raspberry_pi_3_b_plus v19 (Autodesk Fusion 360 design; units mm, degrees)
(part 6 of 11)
sketch "Sketch4" plane through (0, 0, 15.35) normal (0, 0, 1) x axis (-1, 0, 0)
  line L1 (8.5, -21.1878) -> (0.78, -21.1878)
  line L2 (8.5, -6.6286) -> (8.5, -15.9536)
  line L3 (-7.9, -6.6286) -> (8.5, -6.6286)
  line L4 (-7.9, -7.1286) -> (-7.9, -6.6286)
  line L5 (-7.9, -19.2786) -> (-7.9, -7.1286)
  line L6 (-7.9, -19.7786) -> (-7.9, -19.2786)
  line L7 (0.28, -19.7786) -> (-7.9, -19.7786)
  line L8 (0.78, -21.1878) -> (0.78, -19.7786)
  line L9 (7.9563, -25.2118) -> (8.5, -20.7835)
  line L10 (6.5097, -21.514) -> (6.9637, -25.2118)
  line L11 (2.9803, -21.014) -> (6.2597, -21.014)
  line L12 (2.7303, -21.514) -> (2.7303, -21.264)
  line L13 (2.2763, -25.2118) -> (2.7303, -21.514)
  line L14 (0.78, -21.414) -> (0.78, -23.8331)
  line L15 (0.78, -21.1092) -> (1.2837, -25.2118)
  line L16 (7.46, -21.7371) -> (7.46, -25.1508)
  line L17 (8.5, -25.6508) -> (0.78, -25.6508)
  line L18 (6.5097, -21.514) -> (6.5097, -21.264)
  line L19 (1.78, -21.9964) -> (1.78, -25.1508)
  line L20 (0.78, -21.414) -> (8.5, -21.414)
  line L21 (19.0131, 0) -> (0, 0)
  line L22 (7.9563, 25.2118) -> (8.5, 20.7835)
  line L23 (6.5097, 21.514) -> (6.9637, 25.2118)
  line L24 (6.5097, 21.514) -> (6.5097, 21.264)
  line L25 (2.9803, 21.014) -> (6.2597, 21.014)
  line L26 (2.7303, 21.514) -> (2.7303, 21.264)
  line L27 (2.2763, 25.2118) -> (2.7303, 21.514)
  line L28 (0.78, 21.1092) -> (1.2837, 25.2118)
  line L29 (0.78, 21.414) -> (0.78, 23.8331)
  line L30 (0.78, 23.8331) -> (0.78, 24.3609)
  line L31 (0.78, 24.3609) -> (0.78, 25.6508)
  line L32 (0.78, 25.6508) -> (8.5, 25.6508)
  line L33 (8.5, 25.6508) -> (8.5, 24.3609)
  line L34 (8.5, 24.3609) -> (8.5, 23.8331)
  line L35 (8.5, 21.414) -> (8.5, 23.8331)
  line L36 (8.5, 21.1878) -> (8.5, 21.414)
  line L37 (8.5, -24.3609) -> (8.5, -25.6508)
  line L38 (8.5, -23.8331) -> (8.5, -24.3609)
  line L39 (8.5, -21.414) -> (8.5, -23.8331)
  line L40 (0.78, -25.6508) -> (0.78, -24.3609)
  line L41 (0.78, -24.3609) -> (0.78, -23.8331)
  line L42 (8.5, -21.1878) -> (8.5, -21.414)
  line L43 (-7.9, 26.3572) -> (0.28, 26.3572)
  line L44 (0.28, 26.3572) -> (-7.9, 26.3572)
  line L45 (-4.9, 27.3428) -> (-4.9, 26.3572)
  line L46 (-5.5626, 27.3572) -> (-4.2374, 27.3572)
  line L47 (-4.2929, 26.6611) -> (-4.0642, 27.0572)
  line L48 (-5.5071, 26.6611) -> (-5.7358, 27.0572)
  line L49 (-7.9, 20.9572) -> (-7.9, 26.3572)
  line L50 (-4.15, 26.3572) -> (-4.1962, 26.3763)
  line L51 (-5.65, 26.3572) -> (-5.6038, 26.3763)
  line L52 (-5.7256, -26.3572) -> (-5.7015, -26.3472)
  line L53 (-5.629, -26.1336) -> (-5.8665, -25.7222)
  line L54 (-5.65, -25.3472) -> (-4.15, -25.3472)
  line L55 (-4.171, -26.1336) -> (-3.9335, -25.7222)
  line L56 (-4.0744, -26.3572) -> (-4.0985, -26.3472)
  line L57 (0.28, -26.3572) -> (-7.9, -26.3572)
  line L58 (-4.9, -26.3572) -> (-4.9, -25.3472)
  line L59 (-7.9, -26.3572) -> (-7.9, -20.9572)
  line L60 (-8.5786, 5.45) -> (-9.2286, 5.45)
  line L61 (-9.2286, -5.45) -> (-9.2286, 5.45)
  line L62 (-8.5786, 7.1286) -> (-9.2286, 7.1286)
  line L63 (-9.2286, 7.1286) -> (-9.2286, 19.2786)
  line L64 (-8.5786, 19.2786) -> (-9.2286, 19.2786)
  line L65 (-8.5786, -5.45) -> (-9.2286, -5.45)
  line L66 (-8.5786, -7.1286) -> (-9.2286, -7.1286)
  line L67 (-8.5786, 26.3572) -> (-9.2286, 26.3572)
  line L68 (-9.2286, 26.3572) -> (-9.2286, 20.9572)
  line L69 (-9.2286, 20.9572) -> (-9.2286, 26.3572)
  line L70 (-9.2286, 20.9572) -> (-8.5786, 20.9572)
  line L71 (-8.5786, 20.9572) -> (-9.2286, 20.9572)
  line L72 (-9.2286, -7.1286) -> (-9.2286, -19.2786)
  line L73 (-9.2286, -19.2786) -> (-8.5786, -19.2786)
  line L74 (-9.2286, -19.2786) -> (-9.2286, -7.1286)
  line L75 (-8.5786, -20.9572) -> (-9.2286, -20.9572)
  line L76 (-9.2286, -20.9572) -> (-9.2286, -26.3572)
  line L77 (-9.2286, -26.3572) -> (-8.5786, -26.3572)
  line L78 (-9.2286, -26.3572) -> (-9.2286, -20.9572)
  line L79 (-6.9525, -16.1966) -> (-6.9525, -18.2105)
  line L80 (-1.8477, -16.2319) -> (-6.8739, -15.7036)
  line L81 (-1.4, -17.6781) -> (-1.4, -16.7291)
  line L82 (-6.8739, -18.7036) -> (-1.8477, -18.1753)
  line L83 (-1.8477, -8.2319) -> (-6.8739, -7.7036)
  line L84 (-1.4, -9.6781) -> (-1.4, -8.7291)
  line L85 (-6.8739, -10.7036) -> (-1.8477, -10.1753)
  line L86 (-6.9525, -8.1966) -> (-6.9525, -10.2105)
  line L87 (2.5, -16.3786) -> (2.5, -18.0786)
  line L88 (4.2, -16.3786) -> (2.5, -16.3786)
  line L89 (4.2, -18.0786) -> (4.2, -16.3786)
  line L90 (2.5, -18.0786) -> (4.2, -18.0786)
  line L91 (-3.125, -12.5786) -> (-3.125, -13.8286)
  line L92 (4.225, -12.5786) -> (-3.125, -12.5786)
  line L93 (4.225, -13.8286) -> (4.225, -12.5786)
  line L94 (-3.125, -13.8286) -> (4.225, -13.8286)
  line L95 (6.5, -10.8536) -> (6.5, -13.5536)
  line L96 (7.35, -10.7036) -> (6.65, -10.7036)
  line L97 (7.5, -13.5536) -> (7.5, -10.8536)
  line L98 (6.65, -13.7036) -> (7.35, -13.7036)
  line L99 (2.5, -8.3286) -> (2.5, -10.0286)
  line L100 (4.2, -8.3286) -> (2.5, -8.3286)
  line L101 (4.2, -10.0286) -> (4.2, -8.3286)
  line L102 (2.5, -10.0286) -> (4.2, -10.0286)
  line L103 (8.5, -18.4536) -> (8.5, -21.1878)
  line L104 (8, -16.4536) -> (8, -17.9536)
  line L105 (8.5, 21.1878) -> (8.5, 18.4536)
  line L106 (8.5, -6.6286) -> (8.5, -15.9536)
  line L107 (8.5, 15.9536) -> (8.5, 6.6286)
  line L108 (8.5, -18.4536) -> (8.5, -21.1878)
  line L109 (-7.9, -20.9572) -> (-8.5786, -20.9572)
  line L110 (-7.9, -20.4572) -> (-7.9, -20.9572)
  line L111 (-7.9, -20.9572) -> (-7.9, -20.4572)
  line L112 (-7.9, -19.2786) -> (-8.5786, -19.2786)
  line L113 (-7.9, -7.1286) -> (-8.5786, -7.1286)
  line L114 (-7.9, -5.45) -> (-8.5786, -5.45)
  line L115 (-7.9, -5.45) -> (-7.9, -5.95)
  line L116 (-7.9, 5.45) -> (-8.5786, 5.45)
  line L117 (-7.9, 5.95) -> (-7.9, 5.45)
  line L118 (-7.9, 7.1286) -> (-8.5786, 7.1286)
  line L119 (-7.9, 7.1286) -> (-7.9, 6.6286)
  line L120 (-7.9, 19.2786) -> (-8.5786, 19.2786)
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  point P12 (8.5, -20.7835)
  point P28 (0.78, -21.1092)
  point P15 (7.46, -25.1508)
  point P30 (7.46, -25.1508)
  point P25 (1.78, -25.1508)
  point P34 (1.78, -25.1508)
  point P16 (6.5097, -21.514)
  point P22 (2.7303, -21.514)
  point P1 (0, 0)
  point P37 (0, 0)
  point P39 (8.5, 20.7835)
  point P13 (7.9563, -25.2118)
  point P40 (7.9563, 25.2118)
  point P14 (6.9637, -25.2118)
  point P42 (6.9637, 25.2118)
  point P43 (6.5097, 21.514)
  point P17 (6.2597, -21.014)
  point P46 (6.2597, 21.014)
  point P19 (2.9803, -21.014)
  point P47 (2.9803, 21.014)
  point P20 (2.7303, -21.264)
  point P49 (2.7303, 21.264)
  point P50 (2.7303, 21.514)
  point P23 (2.2763, -25.2118)
  point P51 (2.2763, 25.2118)
  point P24 (1.2837, -25.2118)
  point P53 (1.2837, 25.2118)
  point P54 (0.78, 21.1092)
  point P29 (6.5097, -21.264)
  point P44 (6.5097, 21.264)
  point P71 (-4.9, 26.3572)
  point P73 (-4.1962, 26.3763)
  point P82 (-5.6038, 26.3763)
  point P74 (-4.2929, 26.6611)
  point P81 (-5.5071, 26.6611)
  point P76 (-4.2374, 27.3572)
  point P85 (-5.5626, 27.3572)
  point P79 (-4.0642, 27.0572)
  point P83 (-5.7358, 27.0572)
  point P78 (-5.5626, 27.3572)
  point P87 (-4.15, 26.3572)
  point P88 (-5.65, 26.3572)
  point P105 (-4.9, -25.3472)
  point P106 (-4.9, -26.3572)
  point P90 (-5.7015, -26.3472)
  point P101 (-4.0985, -26.3472)
  point P92 (-5.629, -26.1336)
  point P99 (-4.171, -26.1336)
  point P93 (-5.8665, -25.7222)
  point P98 (-3.9335, -25.7222)
  point P89 (-5.7256, -26.3572)
  point P102 (-4.0744, -26.3572)
  point P119 (-9.2286, 25.8572)
  point P118 (-8.7286, 26.3572)
  point P127 (-9.2286, 21.4572)
  point P126 (-8.7286, 20.9572)
  point P132 (-9.2286, 18.7786)
  point P131 (-8.7286, 19.2786)
  point P135 (-9.2286, 7.6286)
  point P134 (-8.7286, 7.1286)
  point P138 (-9.2286, 4.95)
  point P137 (-8.7286, 5.45)
  point P141 (-9.2286, -4.95)
  point P140 (-8.7286, -5.45)
  point P144 (-9.2286, -7.6286)
  point P143 (-8.7286, -7.1286)
  point P149 (-9.2286, -18.7786)
  point P148 (-8.7286, -19.2786)
  point P153 (-8.7286, -20.9572)
  point P160 (-9.2286, -25.8572)
  point P159 (-8.7286, -26.3572)
  point P154 (-9.2286, -21.4572)
  point P240 (-7.9, -19.4286)
  point P239 (-8.05, -19.2786)
  point P245 (-7.9, -6.9786)
  point P244 (-8.05, -7.1286)
  point P248 (-8.05, -5.45)
  point P255 (-7.9, 5.6)
  point P254 (-8.05, 5.45)
  point P261 (-7.9, 6.9786)
  point P260 (-8.05, 7.1286)
  point P266 (-8.05, 19.2786)
  point P232 (-8.05, -20.9572)
  point P233 (-7.9, -20.8072)
  point P249 (-7.9, -5.6)
  point P94 (-5.65, -25.5972)
  point P97 (-4.15, -25.5972)
  coincident L2 P12
  coincident L14 P28
  horizontal L11
  vertical L12
  coincident P15 P30
  vertical L16
  vertical L18
  coincident P25 P34
  vertical L19
  horizontal P16 P22
  coincident P1 P37
  horizontal L21
  symmetric P12 L21 P39
  symmetric P13 L21 P40
  symmetric P14 L21 P42
  symmetric P16 L21 P43
  symmetric P17 L21 P46
  symmetric P19 L21 P47
  symmetric P20 L21 P49
  symmetric P22 L21 P50
  symmetric P23 L21 P51
  symmetric P24 L21 P53
  symmetric P28 L21 P54
  symmetric P29 L21 P44
  coincident L43 P71
  vertical L45
  horizontal L46
  symmetric L45 P73 P82
  symmetric L45 P74 P81
  symmetric L45 P76 P85
  symmetric L45 P79 P83
  coincident P78 P85
  coincident L43 P87
  coincident L43 P88
  midpoint L54 P105
  coincident L57 P106
  vertical L58
  horizontal L54
  symmetric P90 P101 L58
  symmetric P92 P99 L58
  symmetric P93 P98 L58
  coincident P89 L57
  coincident P102 L57
  coincident P119 L68
  coincident P118 L67
  coincident L68 P127
  coincident P126 L70
  coincident L63 P132
  coincident L64 P131
  coincident L63 P135
  coincident L62 P134
  coincident L61 P138
  coincident L60 P137
  coincident L61 P141
  coincident L65 P140
  coincident P144 L72
  coincident L66 P143
  coincident L72 P149
  coincident P148 L73
  coincident P153 L75
  coincident L76 P160
  coincident P159 L77
  coincident P154 L76
  coincident L6 P240
  coincident P239 L112
  coincident L4 P245
  coincident P244 L113
  coincident P248 L114
  coincident P255 L117
  coincident P254 L116
  coincident P261 L119
  coincident P260 L118
  coincident P266 L120
  coincident P232 L109
  coincident P233 L111
  coincident P249 L115
  dimension "d73_4" angle L9 L16 = 7
  dimension "d74_4" angle L10 L16 = 7 (= "d73_4")
  dimension "d75_3" radius = 0.5
  dimension "d77_2" angle L13 L19 = 7 (= "d73_4")
  dimension "d78_2" angle L15 L19 = 7 (= "d73_4")
  dimension "d79_3" distance L11 L20 = 0.4
  dimension "d80_3" radius = 0.25
  dimension "d81_3" distance P16 L11 = 0.5
  dimension "d82_4" distance L16 L19 = 5.68
  dimension "d86_3" distance L44 L46 = 1
  dimension "d87_3" radius = 0.2
  dimension "d89_4" angle L45 L47 = 30
  dimension "d91_4" distance L45 L49 = 3
  dimension "d92_4" distance P82 P88 = 0.05
  dimension "d93_3" distance P87 P88 = 1.5
  dimension "d94_3" angle L43 L51 = 22.5
  dimension "d98_3" angle L53 L58 = 30
  dimension "d99_3" angle L55 L58 = 30
  dimension "d102_3" radius = 0.25
  dimension "d103_3" radius = 0.25
  dimension "d104_3" radius = 0.15
  dimension "d105_2" radius = 0.15
  dimension "d107_3" distance P90 L54 = 1
  dimension "d108_3" distance P94 P97 = 1.5
  dimension "d111_3" distance P90 L57 = 0.01
  dimension "d112_3" angle L52 L57 = 22.5
  dimension "d113_3" distance L58 L59 = 3
  dimension "d115_2" radius = 0.5
  dimension "d224_2" radius = 0.15 (= "d1_4 / 2")
  dimension "d287_2" distance L2 L19 = 6.72 (= "d3_3 - 10.28 mm")
extrude "Extrude4" cut sketch "Sketch4" no distance stored
extrude "Extrude5" add sketch "Sketch4" to an object
extrude "Extrude6" cut sketch "Sketch4" no distance stored
step "Refold1"
face "EdgeFlange9" FlangeHeight 0.85 (= "1 mm - d1_4 / 2") named "d63_4" FlangeAngle 30 named "d64_4"
face "EdgeFlange10" FlangeHeight 1.75 named "d65_4" FlangeAngle 75 named "d66_3"
face "EdgeFlange18" FlangeHeight 1.5 named "d225_3" FlangeAngle 45 named "d226_2"
face "EdgeFlange15" FlangeHeight 1.5 named "d191_2" FlangeAngle 20 named "d192_3" BendWidth 0.1 named "d282_4" BendDepth 0.15 named "d283_4" BendRemnant 0.6 named "d284_1"
face "EdgeFlange16" FlangeHeight 0.601 (= "2 * d1_4 + 0.001 mm") named "d193_3" FlangeAngle 45 named "d194_2" BendWidth 0.05 named "d195_3" BendDepth 0 named "d196_2" BendRemnant 0 named "d197_2"
face "EdgeFlange17" FlangeHeight 3.0015 named "d200_2" FlangeAngle 45 named "d201_2"
step "Unfold2"
extrude "Extrude3" cut sketch "Sketch3" no distance stored
step "Refold2"
sketch "Sketch1" plane through (-8.5, 0, 0) normal (-1, 0, 0) x axis (0, -1, 0)
  line L1 (-6.25, 14.75) -> (-6.25, 5.425)
  line L2 (-6.55, 14.75) -> (-6.25, 14.75)
  line L3 (-6.55, 5.425) -> (-6.55, 14.75)
  line L4 (6.85, 3.3) -> (5.875, 3.3)
  line L5 (5.875, 2.6127) -> (5.875, 1.5)
  line L6 (6.85, 5.05) -> (6.85, 3.3)
  line L7 (5.875, 5.05) -> (6.85, 5.05)
  line L8 (-5.65, 13.04) -> (-5.65, 14.7)
  line L9 (5.65, 14.7) -> (5.65, 13.04)
  line L10 (-5.65, 14.7) -> (5.65, 14.7)
  line L11 (5.74, 12.95) -> (5.74, 5.6179)
  line L12 (5.875, 1.5) -> (-5.875, 1.5)
  line L13 (-5.875, 1.5) -> (-5.875, 2.6127)
  line L14 (-5.74, 5.6179) -> (-5.74, 12.95)
  line L15 (-5.875, 3.3) -> (-6.85, 3.3)
  line L16 (-6.85, 5.05) -> (-5.875, 5.05)
  line L17 (-6.85, 3.3) -> (-6.85, 5.05)
  line L18 (0, 1.5) -> (0, 14.7)
  line L19 (-3.7701, 15.05) -> (3.7701, 15.05)
  line L20 (6.55, 14.25) -> (6.55, 2.1)
  line L21 (-6.25, 5.425) -> (-6.55, 5.425)
  line L22 (-6.25, 0.5951) -> (-6.55, 0.5951)
  line L23 (-6.25, 2.925) -> (-6.25, 0.5951)
  line L24 (-6.55, 2.925) -> (-6.25, 2.925)
  line L25 (-6.55, 0.5951) -> (-6.55, 2.925)
  arc A1 centre (-5.875, 3) radius 0.3 clockwise from (-5.875, 3.3) to (-5.8, 2.7095)
  arc A2 centre (-5.775, 2.6127) radius 0.1 clockwise from (-5.875, 2.6127) to (-5.8, 2.7095)
  arc A3 centre (5.875, 3) radius 0.3 clockwise from (5.8, 2.7095) to (5.875, 3.3)
  arc A4 centre (5.775, 2.6127) radius 0.1 clockwise from (5.8, 2.7095) to (5.875, 2.6127)
  arc A5 centre (-5.875, 5.35) radius 0.3 clockwise from (-5.74, 5.6179) to (-5.875, 5.05)
  arc A6 centre (5.875, 5.35) radius 0.3 clockwise from (5.875, 5.05) to (5.74, 5.6179)
  arc A7 centre (-5.74, 13.04) radius 0.09 clockwise from (-5.65, 13.04) to (-5.74, 12.95)
  arc A8 centre (5.74, 13.04) radius 0.09 clockwise from (5.74, 12.95) to (5.65, 13.04)
  point P24 (0, 14.7)
  point P25 (0, 1.5)
  point P1 (0, 0)
  point P10 (-5.74, 12.95)
  point P14 (5.74, 12.95)
  point P19 (5.74, 5.6179)
  point P20 (-5.74, 5.6179)
  point P11 (-6.85, 5.05)
  point P23 (6.85, 5.05)
  point P15 (-6.85, 3.3)
  point P18 (6.85, 3.3)
  point P28 (6.85, 4.175)
  point P31 (6.55, 8.175)
  point P8 (-5.875, 2.6127)
  point P38 (-5.875, 2.6127)
  point P37 (-5.875, 3)
  point P7 (-5.875, 3.3)
  point P42 (5.875, 3.3)
  point P36 (-5.8, 2.7095)
  point P41 (5.8, 2.7095)
  point P44 (5.875, 2.6127)
  point P17 (5.875, 2.6127)
  point P46 (-5.875, 5.35)
  point P45 (-5.74, 5.6179)
  point P47 (5.875, 5.35)
  point P48 (-5.74, 12.95)
  point P49 (-5.74, 13.04)
  point P51 (5.74, 13.04)
  point P9 (-5.875, 1.5)
  point P12 (5.875, 1.5)
  point P30 (6.55, 14.25)
  horizontal L10
  vertical L8
  vertical L14
  vertical L17
  horizontal L12
  vertical L11
  vertical L9
  vertical L13
  vertical L5
  vertical L6
  perpendicular L15 L17
  perpendicular L16 L17
  perpendicular L4 L6
  perpendicular L6 L7
  midpoint L10 P24
  midpoint L12 P25
  vertical L18
  vertical P1 P25
  symmetric P10 P14 L18
  symmetric P19 P20 L18
  symmetric P11 P23 L18
  symmetric P15 P18 L18
  midpoint L6 P28
  midpoint L20 P31
  tangent L15 A1
  tangent A1 A2
  coincident P8 P38
  coincident L13 P37
  tangent L13 A2
  symmetric P7 L18 P42
  symmetric L18 P36 P41
  symmetric L18 A1 A3
  symmetric L18 P38 P44
  symmetric L18 A2 A4
  coincident P17 P44
  tangent L16 A5
  coincident L13 P46
  equal A1 A5
  coincident P20 P45
  tangent L7 A6
  equal A1 A6
  symmetric L18 P46 P47
  tangent L8 A7
  coincident P10 P48
  tangent L9 A8
  coincident L14 P49
  coincident L11 P51
  dimension "d141_2" distance L10 L12 = 13.2
  dimension "d147_2" distance L4 L7 = 1.75
  dimension "d153_3" distance P9 P12 = 11.75
  dimension "d156_3" distance L6 L17 = 13.7 (= "13.10 mm + 2 * d1_4")
  dimension "d158_3" distance L1 L8 = 0.6 (= "2 * d1_4")
  dimension "d159_3" distance L10 L19 = 0.35 (= "d1_4 + 0.05 mm")
  dimension "d175_2" distance P28 P31 = 4
  dimension "d208_3" radius A1 = 0.3 (= "d1_4")
  dimension "d209_3" radius A2 = 0.1
  dimension "d217_2" distance P14 P30 = 0.81 (= "2.7 * d1_4")
  dimension "d218_3" distance P14 L10 = 1.75
face "Face1" sketch "Sketch1"
face "EdgeFlange3" FlangeHeight 1.5 named "d168_2" FlangeAngle 90 named "d169_2" BendRadius 0.2 named "d170_3"
face "EdgeFlange4" FlangeHeight 2.5 named "d214_3" FlangeAngle 90 named "d215_3" BendRemnant 0.6 named "d219_2" BendRadius 0.2 named "d220_2"
face "EdgeFlange5" FlangeHeight 2 named "d221_2" FlangeAngle 90 named "d222_2"
base_feature "Base Feature1"
work_plane "WorkPlane1" AlongDistance 8.05 named "d228_3"
sketch "Sketch1" plane through (8.05, 0, 0) normal (1, 0, 0) x axis (0, 1, 0)
  line L1 (-6.2, 9.975) -> (6.2, 9.975)
  line L2 (-6.2, 6.375) -> (-6.2, 9.975)
  line L3 (6.2, 6.375) -> (-6.2, 6.375)
  line L4 (6.2, 9.975) -> (6.2, 6.375)
  line L5 (-6.2, 6.375) -> (6.2, 9.975)
  line L6 (6.2, 6.375) -> (-6.2, 9.975)
  line L7 (-4.6, 7.675) -> (-1.1, 7.675)
  line L8 (-4.6, 8.675) -> (-4.6, 7.675)
  line L9 (-1.1, 8.675) -> (-4.6, 8.675)
  line L10 (-1.1, 7.675) -> (-1.1, 8.675)
  line L11 (-4.6, 8.675) -> (-1.1, 7.675)
  line L12 (-1.1, 8.675) -> (-4.6, 7.675)
  line L13 (0, 9.4362) -> (0, 8.175)
  line L14 (1.1, 8.675) -> (4.6, 8.675)
  line L15 (1.1, 7.675) -> (1.1, 8.675)
  line L16 (4.6, 7.675) -> (1.1, 7.675)
  line L17 (4.6, 8.675) -> (4.6, 7.675)
  point P6 (0, 8.175)
  point P1 (0, 0)
  point P7 (-6.55, 8.175)
  point P12 (-2.85, 8.175)
  point P13 (0, 8.175)
  point P8 (-1.1, 7.675)
  point P17 (1.1, 7.675)
  point P9 (-4.6, 7.675)
  point P18 (4.6, 7.675)
  point P10 (-4.6, 8.675)
  point P15 (4.6, 8.675)
  point P11 (-1.1, 8.675)
  point P16 (1.1, 8.675)
  point P4 (-6.2, 6.375)
  point P5 (6.2, 6.375)
  point P3 (-6.2, 9.975)
  perpendicular L1 L2
  parallel L1 L3
  parallel L2 L4
  horizontal L1
  coincident L5 P6
  coincident L6 P6
  vertical P1 P6
  horizontal P6 P7
  perpendicular L7 L8
  parallel L7 L9
  parallel L8 L10
  horizontal L7
  coincident L11 P12
  coincident L12 P12
  coincident P6 P13
  vertical L13
  symmetric P8 L13 P17
  symmetric P9 L13 P18
  symmetric P10 L13 P15
  symmetric P11 L13 P16
  horizontal P6 P12
  dimension "d229_3" distance P4 P5 = 12.4
  dimension "d230_2" distance P3 P4 = 3.6 (= "3 mm + d1_4 * 2")
  dimension "d231_2" distance P10 P11 = 3.5
  dimension "d232_3" distance P9 P10 = 1
  dimension "d233_3" distance L10 L13 = 1.1
face "Face1" sketch "Sketch1"
face "EdgeFlange2" FlangeHeight 8.5 named "d234_3" FlangeAngle 90 named "d235_3"
extrude "Extrude6" cut sketch "Sketch1" profile of L7 L8 L9 L10 L14 L15 L16 L17 no distance stored
face "EdgeFlange3" FlangeHeight 2.5 named "d236_3" FlangeAngle 20 named "d237_3" BendRemnant 0 named "d240_3" BendWidth 0.01 named "d243_3" BendDepth 0 named "d244_3"
face "EdgeFlange4" FlangeHeight 1 named "d241_3" FlangeAngle 20 (= "d237_3") named "d242_3"
sketch "Sketch3" plane through (0, 0, 9.975) normal (0, 0, 1) x axis (-1, 0, 0)
  line L1 (-7.75, -6.2) -> (-7.75, 6.2)
  line L2 (0.15, -6.2) -> (-7.75, -6.2)
  line L3 (0.15, 6.2) -> (0.15, -6.2)
  line L4 (-7.75, 6.2) -> (0.15, 6.2)
  line L5 (-7.35, -2.132) -> (-7.35, -3.868)
  line L6 (-7.0487, -4.2146) -> (-2.35, -4.875)
  line L7 (-2.35, -3) -> (-7.35, -3)
  line L8 (-2.35, -1.125) -> (-2.35, -4.875)
  line L9 (-7.0487, -1.7854) -> (-2.35, -1.125)
  line L10 (-8.35, 6.2) -> (-8.35, -6.2)
  line L11 (-13, 0) -> (0, 0)
  line L12 (-7.0487, 1.7854) -> (-2.35, 1.125)
  line L13 (-7.35, 2.132) -> (-7.35, 3.868)
  line L14 (-7.0487, 4.2146) -> (-2.35, 4.875)
  line L15 (-2.35, 1.125) -> (-2.35, 4.875)
  arc A1 centre (-7, -3.868) radius 0.35 clockwise from (-7.0487, -4.2146) to (-7.35, -3.868)
  arc A2 centre (-7, -2.132) radius 0.35 clockwise from (-7.35, -2.132) to (-7.0487, -1.7854)
  arc A3 centre (-7, 2.132) radius 0.35 clockwise from (-7.0487, 1.7854) to (-7.35, 2.132)
  arc A4 centre (-7, 3.868) radius 0.35 clockwise from (-7.35, 3.868) to (-7.0487, 4.2146)
  point P14 (-2.35, -1.125)
  point P15 (-2.35, -4.875)
  point P16 (-2.35, -1.125)
  point P7 (-7.35, -3)
  point P6 (-7.0487, -1.7854)
  point P12 (-7.0487, -4.2146)
  point P17 (-2.35, -3)
  point P1 (0, 0)
  point P21 (0, 0)
  point P24 (-7.0487, 1.7854)
  point P10 (-7.35, -3.868)
  point P27 (-7.35, 3.868)
  point P29 (-7.0487, 4.2146)
  point P13 (-7.35, -2.132)
  point P26 (-7.35, 2.132)
  point P23 (-2.35, 1.125)
  point P30 (-2.35, 4.875)
  point P31 (-2.35, 1.125)
  point P9 (-2.35, 3)
  symmetric P14 P15 L7
  coincident P14 P16
  coincident P7 L5
  tangent L6 A1
  tangent L5 A1
  tangent L5 A2
  tangent A2 L9
  equal A1 A2
  symmetric P6 P12 L7
  coincident P17 L8
  coincident P1 P21
  horizontal L11
  symmetric P6 L11 P24
  symmetric P10 L11 P27
  symmetric P12 L11 P29
  symmetric P13 L11 P26
  symmetric P14 L11 P23
  symmetric P15 L11 P30
  symmetric P16 L11 P31
  symmetric A1 L11 A4
  symmetric A2 L11 A3
  midpoint P9 L15
  dimension "d260_3" distance P9 L7 = 6
  dimension "d261_2" angle L6 L8 = 82
  dimension "d262_2" radius A1 = 0.35
  dimension "d263_2" distance L5 L8 = 5
  dimension "d264_4" distance P15 P16 = 3.75
  dimension "d265_4" distance L5 L10 = 1
extrude "Extrude2" cut sketch "Sketch3" profile of L5 L6 A1 L8 A2 L9 L12 A3 L13 A4 L14 L15 no distance stored
face "EdgeFlange6" FlangeHeight 2.5 named "d267_4" FlangeAngle 10 named "d268_4" BendWidth 0.5 named "d269_4" BendDepth 0.3 named "d270_4" BendRemnant 0.6 named "d271_4"
step "Unfold2"
sketch "Sketch4" plane through (8.35, 0, 0) normal (1, 0, 0) x axis (0, 1, 0)
  line L1 (6.2, 6.975) -> (-6.2, 6.975)
  line L2 (6.2, 9.375) -> (6.2, 6.975)
  line L3 (-6.2, 9.375) -> (6.2, 9.375)
  line L4 (-6.2, 6.975) -> (-6.2, 9.375)
  line L5 (-3.7536, 11.1257) -> (-4.3774, 15.5646)
  line L6 (-2.4445, 10.9536) -> (-3.5555, 10.9536)
  line L7 (-1.6226, 15.5646) -> (-2.2464, 11.1257)
  line L8 (-1.7854, 10.7549) -> (-1.1601, 15.2036)
  line L9 (-4.8399, 15.2036) -> (-4.2146, 10.7549)
  line L10 (-3.868, 10.4536) -> (-2.132, 10.4536)
  line L11 (-4.875, 15.4536) -> (-4.8399, 15.2036)
  line L12 (-4.875, 15.5298) -> (-4.875, 15.2036)
  line L13 (-4.875, 15.2036) -> (-4.875, 15.5298)
  line L14 (-4.875, 15.2036) -> (-4.8399, 15.2036)
  line L15 (-1.125, 15.4536) -> (-1.1601, 15.2036)
  line L16 (-1.125, 15.2036) -> (-1.125, 15.5298)
  line L17 (-1.125, 15.5298) -> (-1.125, 15.2036)
  line L18 (-1.1601, 15.2036) -> (-1.125, 15.2036)
  line L19 (0, 22.1983) -> (0, 0)
  line L20 (4.875, 15.2036) -> (4.875, 15.5298)
  line L21 (1.125, 15.5298) -> (1.125, 15.2036)
  line L22 (1.125, 15.2036) -> (1.1601, 15.2036)
  line L23 (4.8399, 15.2036) -> (4.875, 15.2036)
  line L24 (1.1601, 15.2036) -> (1.125, 15.2036)
  line L25 (1.1601, 15.2036) -> (1.7854, 10.7549)
  line L26 (2.132, 10.4536) -> (3.868, 10.4536)
  line L27 (4.2146, 10.7549) -> (4.8399, 15.2036)
  line L28 (1.125, 15.4536) -> (1.1601, 15.2036)
  line L29 (4.875, 15.4536) -> (4.8399, 15.2036)
  line L30 (3.7536, 11.1257) -> (4.3774, 15.5646)
  line L31 (2.4445, 10.9536) -> (3.5555, 10.9536)
  line L32 (1.6226, 15.5646) -> (2.2464, 11.1257)
  line L33 (6.2, 8.175) -> (-6.2, 8.175)
  line L34 (-3.7536, 5.2243) -> (-4.3774, 0.7854)
  line L35 (-2.4445, 5.3964) -> (-3.5555, 5.3964)
  line L36 (-1.6226, 0.7854) -> (-2.2464, 5.2243)
  line L37 (3.7536, 5.2243) -> (4.3774, 0.7854)
  line L38 (2.4445, 5.3964) -> (3.5555, 5.3964)
  line L39 (1.6226, 0.7854) -> (2.2464, 5.2243)
  line L40 (-4.875, 0.8964) -> (-4.8399, 1.1464)
  line L41 (-1.125, 0.8964) -> (-1.1601, 1.1464)
  line L42 (1.125, 0.8964) -> (1.1601, 1.1464)
  line L43 (4.875, 0.8964) -> (4.8399, 1.1464)
  line L44 (-4.875, 1.1464) -> (-4.875, 0.8202)
  line L45 (-4.8399, 1.1464) -> (-4.875, 1.1464)
  line L46 (-4.2146, 5.5951) -> (-4.8399, 1.1464)
  line L47 (-1.1601, 1.1464) -> (-1.7854, 5.5951)
  line L48 (-1.125, 0.8202) -> (-1.125, 1.1464)
  line L49 (-1.125, 1.1464) -> (-1.1601, 1.1464)
  line L50 (-2.132, 5.8964) -> (-3.868, 5.8964)
  line L51 (1.125, 1.1464) -> (1.125, 0.8202)
  line L52 (1.1601, 1.1464) -> (1.125, 1.1464)
  line L53 (1.7854, 5.5951) -> (1.1601, 1.1464)
  line L54 (4.875, 0.8202) -> (4.875, 1.1464)
  line L55 (4.875, 1.1464) -> (4.8399, 1.1464)
  line L56 (4.8399, 1.1464) -> (4.2146, 5.5951)
  line L57 (3.868, 5.8964) -> (2.132, 5.8964)
  arc A1 centre (-3.5555, 11.1536) radius 0.2 clockwise from (-3.5555, 10.9536) to (-3.7536, 11.1257)
  arc A2 centre (-2.4445, 11.1536) radius 0.2 clockwise from (-2.2464, 11.1257) to (-2.4445, 10.9536)
  arc A3 centre (-4.625, 15.5298) radius 0.25 clockwise from (-4.875, 15.5298) to (-4.375, 15.5298)
  arc A4 centre (-1.375, 15.5298) radius 0.25 clockwise from (-1.625, 15.5298) to (-1.125, 15.5298)
  arc A5 centre (-1.375, 15.5298) radius 0.25 clockwise from (-1.625, 15.5298) to (-1.125, 15.5298)
  arc A6 centre (-3.868, 10.8036) radius 0.35 clockwise from (-3.868, 10.4536) to (-4.2146, 10.7549)
  arc A7 centre (-2.132, 10.8036) radius 0.35 clockwise from (-1.7854, 10.7549) to (-2.132, 10.4536)
  arc A8 centre (1.375, 15.5298) radius 0.25 clockwise from (1.125, 15.5298) to (1.625, 15.5298)
  arc A9 centre (4.625, 15.5298) radius 0.25 clockwise from (4.375, 15.5298) to (4.875, 15.5298)
  arc A10 centre (2.132, 10.8036) radius 0.35 clockwise from (2.132, 10.4536) to (1.7854, 10.7549)
  arc A11 centre (3.868, 10.8036) radius 0.35 clockwise from (4.2146, 10.7549) to (3.868, 10.4536)
  arc A12 centre (3.5555, 11.1536) radius 0.2 clockwise from (3.7536, 11.1257) to (3.5555, 10.9536)
  arc A13 centre (2.4445, 11.1536) radius 0.2 clockwise from (2.4445, 10.9536) to (2.2464, 11.1257)
  arc A14 centre (-3.5555, 5.1964) radius 0.2 clockwise from (-3.7536, 5.2243) to (-3.5555, 5.3964)
  arc A15 centre (-2.4445, 5.1964) radius 0.2 clockwise from (-2.4445, 5.3964) to (-2.2464, 5.2243)
  arc A16 centre (3.5555, 5.1964) radius 0.2 clockwise from (3.5555, 5.3964) to (3.7536, 5.2243)
  arc A17 centre (2.4445, 5.1964) radius 0.2 clockwise from (2.2464, 5.2243) to (2.4445, 5.3964)
  arc A18 centre (-4.625, 0.8202) radius 0.25 clockwise from (-4.375, 0.8202) to (-4.875, 0.8202)
  arc A19 centre (-1.375, 0.8202) radius 0.25 clockwise from (-1.125, 0.8202) to (-1.625, 0.8202)
  arc A20 centre (-2.132, 5.5464) radius 0.35 clockwise from (-2.132, 5.8964) to (-1.7854, 5.5951)
  arc A21 centre (-3.868, 5.5464) radius 0.35 clockwise from (-4.2146, 5.5951) to (-3.868, 5.8964)
  arc A22 centre (1.375, 0.8202) radius 0.25 clockwise from (1.625, 0.8202) to (1.125, 0.8202)
  arc A23 centre (4.625, 0.8202) radius 0.25 clockwise from (4.875, 0.8202) to (4.375, 0.8202)
  arc A24 centre (2.132, 5.5464) radius 0.35 clockwise from (1.7854, 5.5951) to (2.132, 5.8964)
  arc A25 centre (3.868, 5.5464) radius 0.35 clockwise from (3.868, 5.8964) to (4.2146, 5.5951)
  point P17 (-4.8399, 15.2036)
  point P20 (-4.8399, 15.2036)
  point P21 (-4.875, 15.4536)
  point P6 (-4.3774, 15.5646)
  point P13 (-1.6226, 15.5646)
  point P14 (-1.1601, 15.2036)
  point P34 (-1.1601, 15.2036)
  point P35 (-1.125, 15.4536)
  point P1 (0, 0)
  point P38 (0, 0)
  point P53 (1.1601, 15.2036)
  point P60 (1.1601, 15.2036)
  point P51 (4.8399, 15.2036)
  point P62 (4.8399, 15.2036)
  point P63 (4.875, 15.4536)
  point P61 (1.125, 15.4536)
  point P64 (4.3774, 15.5646)
  point P7 (-3.7536, 11.1257)
  point P65 (3.7536, 11.1257)
  point P8 (-3.5555, 10.9536)
  point P67 (3.5555, 10.9536)
  point P10 (-2.4445, 10.9536)
  point P68 (2.4445, 10.9536)
  point P11 (-2.2464, 11.1257)
  point P70 (2.2464, 11.1257)
  point P71 (1.6226, 15.5646)
  point P72 (-6.2, 8.175)
  point P73 (6.2, 8.175)
  point P74 (-4.3774, 0.7854)
  point P75 (-3.7536, 5.2243)
  point P77 (-3.5555, 5.3964)
  point P78 (-2.4445, 5.3964)
  point P80 (-2.2464, 5.2243)
  point P81 (-1.6226, 0.7854)
  point P90 (-4.8399, 1.1464)
  point P91 (-4.875, 0.8964)
  point P92 (-1.1601, 1.1464)
  point P93 (-1.125, 0.8964)
  point P94 (1.1601, 1.1464)
  point P95 (1.125, 0.8964)
  point P96 (4.8399, 1.1464)
  point P97 (4.875, 0.8964)
  point P82 (4.3774, 0.7854)
  point P83 (3.7536, 5.2243)
  point P85 (3.5555, 5.3964)
  point P86 (2.4445, 5.3964)
  point P88 (2.2464, 5.2243)
  point P89 (1.6226, 0.7854)
  tangent L5 A1
  tangent L6 A2
  parallel L7 L8
  parallel L5 L9
  parallel L6 L10
  tangent A2 L7
  tangent A1 L6
  coincident P17 P20
  parallel L9 L11
  coincident P21 L12
  coincident P6 A3
  tangent L5 A3
  coincident P13 A4
  tangent L7 A5
  coincident P14 P34
  parallel L8 L15
  coincident P35 L16
  coincident P1 P38
  vertical L19
  equal A1 A2
  coincident P53 P60
  parallel L25 L28
  coincident P51 P62
  parallel L27 L29
  coincident L20 P63
  coincident L21 P61
  symmetric P6 L19 P64
  symmetric P7 L19 P65
  symmetric P8 L19 P67
  symmetric A1 L19 A12
  symmetric P10 L19 P68
  symmetric P11 L19 P70
  symmetric A2 L19 A13
  symmetric P13 L19 P71
  midpoint L4 P72
  midpoint L2 P73
  symmetric P6 L33 P74
  symmetric P7 L33 P75
  symmetric P8 L33 P77
  symmetric A1 L33 A14
  symmetric P10 L33 P78
  symmetric P11 L33 P80
  symmetric A2 L33 A15
  symmetric P13 L33 P81
  symmetric P20 L33 P90
  symmetric P21 L33 P91
  symmetric P34 L33 P92
  symmetric P35 L33 P93
  symmetric P60 L33 P94
  symmetric P61 L33 P95
  symmetric P62 L33 P96
  symmetric P63 L33 P97
  symmetric P64 L33 P82
  symmetric P65 L33 P83
  symmetric P67 L33 P85
  symmetric A12 L33 A16
  symmetric P68 L33 P86
  symmetric P70 L33 P88
  symmetric A13 L33 A17
  symmetric P71 L33 P89
  dimension "d272_4" distance L6 L10 = 0.5
  dimension "d273_4" radius A1 = 0.2
extrude "Extrude3" add sketch "Sketch4" profile of L11 L12 L13 L14 L15 L16 L17 L18 L20 L21 L22 L23 L24 L28 L29 L40 L41 L42 L43 L44 L45 L48 L49 L51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 against normal blind 0.3 named "d274_4"
extrude "Extrude4" cut sketch "Sketch4" profile of L5 A1 L6 A2 L7 L8 L9 L10 L11 L12 L13 A3 A4 A5 L15 L16 L17 A6 A7 A8 A9 L20 L21 L25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 no distance stored
step "Refold2"
face "EdgeFlange7" FlangeHeight 0.75 named "d277_4" FlangeAngle 30 named "d278_4"
face "EdgeFlange8" FlangeHeight 2 named "d279_4" FlangeAngle 72 named "d280_4"
step "Unfold3"
extrude "Extrude5" cut sketch "Sketch4" profile of L5 A1 L6 A2 L7 L8 L9 L10 L11 L12 L13 A3 A4 A5 L15 L16 L17 A6 A7 A8 A9 L20 L21 L25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 no distance stored
step "Refold3"
work_plane "WorkPlane1" AlongDistance -15.76 (= "-10.28 mm - 2.71 mm - 2.62 mm - 0.15 mm") named "d288_2"
sketch "Sketch1" plane through (-7.26, 0, 15.975) normal (1, 0, 0) x axis (0, 1, 0)
  line L1 (3.8, -18.2428) -> (3.5893, -18.775)
  line L2 (3.8, -2.175) -> (3.8, -13.7834)
  line L3 (3.2, -13.7834) -> (3.2, -2.175)
  line L4 (3.8, -15.1666) -> (3.8, -18.2428)
  line L5 (3.9928, -14.3132) -> (3.8, -14.475)
  line L6 (3.2, -18.2533) -> (3.2, -15.1666)
  line L7 (3.2, -2.175) -> (3.8, -2.175)
  line L8 (3.5893, -18.775) -> (3.4107, -18.775)
  line L9 (3.4107, -18.775) -> (3.2, -18.2533)
  line L10 (3.7701, -0.925) -> (-3.7701, -0.925)
  line L11 (3.5, -18.775) -> (3.5, -2.175)
  line L12 (3.2, -14.475) -> (3.8, -14.475)
  line L13 (3.9928, -14.6368) -> (3.8, -14.475)
  line L14 (3.0072, -14.3132) -> (3.2, -14.475)
  line L15 (3.0072, -14.6368) -> (3.2, -14.475)
  arc A1 centre (3.8, -14.0834) radius 0.3 clockwise from (3.8, -13.7834) to (3.9928, -14.3132)
  arc A2 centre (3.8, -14.8666) radius 0.3 clockwise from (3.9928, -14.6368) to (3.8, -15.1666)
  arc A3 centre (3.2, -14.0834) radius 0.3 clockwise from (3.0072, -14.3132) to (3.2, -13.7834)
  arc A4 centre (3.2, -14.8666) radius 0.3 clockwise from (3.2, -15.1666) to (3.0072, -14.6368)
  point P5 (3.8, -14.0834)
  point P8 (3.8, -14.475)
  point P6 (3.9928, -14.3132)
  point P9 (3.9928, -14.3132)
  point P19 (3.5, -2.175)
  point P20 (3.5, -18.775)
  point P23 (3.9928, -14.6368)
  point P25 (3.8, -14.475)
  point P26 (3.9928, -14.6368)
  point P14 (3.8, -13.7834)
  point P24 (3.8, -15.1666)
  point P13 (3.8, -15.1666)
  point P28 (3.0072, -14.3132)
  point P30 (3.2, -14.475)
  point P31 (3.0072, -14.3132)
  point P29 (3.2, -13.7834)
  point P36 (3.0072, -14.6368)
  point P35 (3.2, -15.1666)
  point P32 (3.2, -14.475)
  point P33 (3.0072, -14.6368)
  point P4 (3.2, -13.7834)
  point P12 (3.2, -15.1666)
  point P21 (3.2, -14.475)
  point P18 (0, -15.975)
  point P1 (0, 0)
  vertical L3
  vertical L2
  coincident P5 L2
  coincident P8 L2
  collinear L2 L4
  collinear L3 L6
  horizontal L8
  horizontal L7
  coincident P6 P9
  tangent A1 L5
  midpoint L7 P19
  midpoint L8 P20
  horizontal L12
  symmetric P6 L12 P23
  symmetric P8 L12 P25
  symmetric P9 L12 P26
  symmetric P14 L12 P24
  symmetric A1 L12 A2
  coincident P23 P26
  coincident P13 P24
  coincident P8 P25
  symmetric P6 L11 P28
  symmetric P8 L11 P30
  symmetric P9 L11 P31
  symmetric P14 L11 P29
  symmetric A1 L11 A3
  symmetric L11 P23 P36
  symmetric L11 P24 P35
  symmetric L11 A2 A4
  symmetric L11 P25 P32
  symmetric L11 P26 P33
  coincident P4 P29
  coincident P12 P35
  coincident P21 P30
  dimension "d289_2" distance L2 L3 = 0.6
  dimension "d293_2" distance L7 L10 = 1.25
  dimension "d295_2" distance L8 P18 = 2.8
  dimension "d298_2" angle L2 L5 = 50
  dimension "d299_2" radius A1 = 0.3
  dimension "d300_2" distance P18 L12 = 1.5
  dimension "d301_2" distance P1 L11 = 3.5 (= "( 7 / 2 ) * 1 mm")
face "Face1" sketch "Sketch1"
face "EdgeFlange2" FlangeHeight 4 named "d302_2" FlangeAngle 90 named "d303_2"
sketch "Sketch2" plane through (0, 0, 13.8) normal (0, 0, 1) x axis (-1, 0.0001, 0)
  line L1 (6.9604, -3.1991) -> (6.9605, -3.7992)
  line L2 (3.5604, -3.1996) -> (6.9604, -3.1991)
  line L3 (3.5605, -3.7996) -> (3.5604, -3.1996)
  line L4 (6.9605, -3.7992) -> (3.5605, -3.7996)
  line L5 (7.5605, -3.7991) -> (7.5604, -3.1991)
  line L6 (2.7854, -4.1587) -> (2.7354, -4.1587)
  line L7 (3.9604, -4.0649) -> (3.9604, -4.1089)
  line L8 (2.1854, -4.1587) -> (1.4604, -4.1587)
  line L9 (2.9747, -4.2241) -> (2.8668, -4.176)
  line L10 (3.8604, -4.2089) -> (3.528, -4.2089)
  line L11 (3.4515, -4.2241) -> (2.9747, -4.2241)
  line L12 (1.4604, -4.1587) -> (1.4604, -2.8394)
  line L13 (7.5604, -3.4991) -> (1.4604, -3.4991)
  line L14 (6.9605, -3.7992) -> (3.5605, -3.7996)
  line L15 (2.1854, -2.8394) -> (1.4604, -2.8394)
  line L16 (2.7854, -2.8394) -> (2.7354, -2.8394)
  line L17 (2.9747, -2.7741) -> (2.8668, -2.8221)
  line L18 (3.4515, -2.7741) -> (2.9747, -2.7741)
  line L19 (3.8604, -2.7893) -> (3.528, -2.7893)
  line L20 (3.9604, -2.9332) -> (3.9604, -2.8893)
  line L21 (1.3604, -4.1319) -> (1.0901, -3.9759)
  line L22 (1.4604, -4.1587) -> (1.4604, -4.1587)
  line L23 (0.45, -3.9491) -> (0.9901, -3.9491)
  line L24 (1.3604, -2.8662) -> (1.0901, -3.0223)
  line L25 (0.9901, -3.9491) -> (0.9901, -3.0491)
  line L26 (3.5605, -3.7996) -> (3.5604, -3.1996)
  line L27 (0.8339, -4.1587) -> (1.4604, -4.1587)
  line L28 (0.8339, -2.8339) -> (0.8339, -4.1587)
  line L29 (1.4604, -2.8394) -> (0.8339, -2.8339)
  arc A1 centre (3.528, -4.4089) radius 0.2 clockwise from (3.4515, -4.2241) to (3.528, -4.2089)
  arc A2 centre (4.2269, -3.6495) radius 0.15 clockwise from (4.2269, -3.7995) to (4.1436, -3.7743)
  arc A3 centre (4.0604, -3.8991) radius 0.15 clockwise from (3.9354, -3.982) to (4.1436, -3.7743)
  arc A4 centre (3.8104, -4.0649) radius 0.15 clockwise from (3.9354, -3.982) to (3.9604, -4.0649)
  arc A5 centre (3.8604, -4.1089) radius 0.1 clockwise from (3.9604, -4.1089) to (3.8604, -4.2089)
  arc A6 centre (2.7854, -4.3587) radius 0.2 clockwise from (2.7854, -4.1587) to (2.8668, -4.176)
  arc A7 centre (2.7354, -4.3587) radius 0.2 clockwise from (2.5979, -4.2135) to (2.7354, -4.1587)
  arc A8 centre (2.4604, -4.0683) radius 0.2 clockwise from (2.5979, -4.2135) to (2.3229, -4.2135)
  arc A9 centre (2.1854, -4.3587) radius 0.2 clockwise from (2.1854, -4.1587) to (2.3229, -4.2135)
  arc A10 centre (2.1854, -2.6394) radius 0.2 clockwise from (2.3229, -2.7847) to (2.1854, -2.8394)
  arc A11 centre (2.7354, -2.6394) radius 0.2 clockwise from (2.7354, -2.8394) to (2.5979, -2.7847)
  arc A12 centre (2.7854, -2.6394) radius 0.2 clockwise from (2.8668, -2.8221) to (2.7854, -2.8394)
  arc A13 centre (3.528, -2.5893) radius 0.2 clockwise from (3.528, -2.7893) to (3.4515, -2.7741)
  arc A14 centre (3.8604, -2.8893) radius 0.1 clockwise from (3.8604, -2.7893) to (3.9604, -2.8893)
  arc A15 centre (3.8104, -2.9332) radius 0.15 clockwise from (3.9604, -2.9332) to (3.9354, -3.0162)
  arc A16 centre (4.0604, -3.0991) radius 0.15 clockwise from (4.1436, -3.2239) to (3.9354, -3.0162)
  arc A17 centre (4.2269, -3.3487) radius 0.15 clockwise from (4.1436, -3.2239) to (4.2269, -3.1987)
  arc A18 centre (2.4604, -2.9299) radius 0.2 clockwise from (2.3229, -2.7847) to (2.5979, -2.7847)
  arc A19 centre (1.4604, -3.9587) radius 0.2 clockwise from (1.4604, -4.1587) to (1.3604, -4.1319)
  arc A20 centre (0.9901, -4.1491) radius 0.2 clockwise from (0.9901, -3.9491) to (1.0901, -3.9759)
  arc A21 centre (0.9901, -2.8491) radius 0.2 clockwise from (1.0901, -3.0223) to (0.9901, -3.0491)
  arc A22 centre (1.4604, -3.0394) radius 0.2 clockwise from (1.3604, -2.8662) to (1.4604, -2.8394)
  point P32 (2.7604, -4.1587)
  point P35 (1.4604, -3.4991)
  point P33 (2.3229, -4.2135)
  point P37 (2.3229, -4.2135)
  point P36 (7.5604, -3.4991)
  point P11 (4.2269, -3.7995)
  point P22 (1.4604, -4.1587)
  point P38 (1.4604, -4.1587)
  point P9 (4.1436, -3.7743)
  point P62 (4.1436, -3.2239)
  point P10 (3.9604, -4.1089)
  point P57 (3.9604, -2.8893)
  point P64 (4.2269, -3.1987)
  point P12 (3.4515, -4.2241)
  point P52 (3.4515, -2.7741)
  point P13 (3.528, -4.2089)
  point P54 (3.528, -2.7893)
  point P14 (2.8668, -4.176)
  point P50 (2.8668, -2.8221)
  point P16 (3.8604, -4.2089)
  point P55 (3.8604, -2.7893)
  point P17 (3.9354, -3.982)
  point P60 (3.9354, -3.0162)
  point P18 (2.9747, -4.2241)
  point P51 (2.9747, -2.7741)
  point P19 (3.9604, -4.0649)
  point P58 (3.9604, -2.9332)
  point P20 (2.7854, -4.1587)
  point P48 (2.7854, -2.8394)
  point P21 (2.7354, -4.1587)
  point P46 (2.7354, -2.8394)
  point P41 (1.4604, -2.8394)
  point P23 (2.1854, -4.1587)
  point P42 (2.1854, -2.8394)
  point P29 (2.5979, -4.2135)
  point P47 (2.5979, -2.7847)
  point P44 (2.3229, -2.7847)
  point P66 (2.3229, -2.7847)
  point P8 (1.4604, -2.8394)
  point P78 (1.4604, -2.8394)
  point P67 (1.3604, -4.1319)
  point P76 (1.3604, -2.8662)
  point P69 (0.9901, -3.9491)
  point P75 (0.9901, -3.0491)
  point P71 (1.0901, -3.9759)
  point P74 (1.0901, -3.0223)
  point P25 (4.0604, -3.8991)
  point P31 (2.4604, -4.0683)
  horizontal L8
  horizontal L11
  horizontal L10
  vertical L7
  vertical L12
  tangent A2 A3
  tangent A3 A4
  tangent L7 A4
  tangent L7 A5
  tangent A1 L10
  tangent L10 A5
  horizontal L6
  tangent L9 A6
  tangent L6 A6
  tangent L6 A7
  tangent A7 A8
  midpoint L6 P32
  tangent L8 A9
  collinear L6 L8
  midpoint L12 P35
  horizontal L13
  coincident P33 P37
  tangent A8 A9
  midpoint L5 P36
  coincident L4 P11
  tangent L4 A2
  coincident P22 P38
  symmetric P9 L13 P62
  symmetric P10 L13 P57
  symmetric P11 L13 P64
  symmetric P12 L13 P52
  symmetric P13 L13 P54
  symmetric P14 L13 P50
  symmetric P16 L13 P55
  symmetric P17 L13 P60
  symmetric P18 L13 P51
  symmetric P19 L13 P58
  symmetric P20 L13 P48
  symmetric P21 L13 P46
  symmetric P22 L13 P41
  symmetric P23 L13 P42
  symmetric A1 L13 A13
  symmetric A2 L13 A17
  symmetric A3 L13 A16
  symmetric A4 L13 A15
  symmetric A5 L13 A14
  symmetric A6 L13 A12
  symmetric P29 L13 P47
  symmetric A7 L13 A11
  symmetric A8 L13 A18
  symmetric P33 L13 P44
  symmetric A9 L13 A10
  symmetric L13 P37 P66
  coincident P8 P41
  perpendicular L12 L22
  tangent L8 A19
  horizontal L23
  tangent L21 A19
  tangent L21 A20
  equal A19 A20
  tangent L23 A20
  symmetric P22 L13 P78
  symmetric L13 P67 P76
  symmetric L13 A19 A22
  symmetric L13 P69 P75
  symmetric L13 P71 P74
  symmetric L13 A20 A21
  horizontal L27
  perpendicular L27 L28
  dimension "d304_2" = 0.15
  dimension "d305_2" radius A3 = 0.15
  dimension "d306_2" radius A4 = 0.15
  dimension "d307_2" radius A5 = 0.1
  dimension "d308_2" radius A1 = 0.2
  dimension "d309_2" angle L9 L11 = 24
  dimension "d310_2" distance L7 P32 = 1.2
  dimension "d311_2" radius A6 = 0.2
  dimension "d312_2" radius A7 = 0.2
  dimension "d313_2" radius A8 = 0.2
  dimension "d314_2" distance P20 P21 = 0.05
  dimension "d316_2" distance L8 L13 = 0.6597
  dimension "d317_2" distance P25 L13 = 0.4
  dimension "d319_2" distance L10 L13 = 0.7098
  dimension "d321_2" radius A9 = 0.2
  dimension "d323_2" distance L11 L13 = 0.725
  dimension "d326_2" distance P25 P36 = 3.5
  dimension "d327_2" distance L7 P31 = 1.5
  dimension "d328_2" distance P10 P22 = 2.5
  dimension "d329_2" distance L7 P25 = 0.1
  dimension "d331_2" distance L13 L23 = 0.45
  dimension "d334_2" angle L13 L21 = 30
  dimension "d336_2" radius A19 = 0.2
extrude "Extrude1" cut sketch "Sketch2" profile of L2 L4 A2 A3 L14 A16 A17 against normal blind 0.45 named "d338_2"
extrude "Extrude2" add sketch "Sketch2" profile of L2 L4 L6 A1 L7 L8 L9 L10 L11 L12 A3 A4 A5 A6 A7 A8 A9 L14 L15 A10 A11 L16 A12 L17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 against normal blind 0.3 named "d340_2"
face "EdgeFlange3" FlangeHeight 0.43 named "d342_2" FlangeAngle 20 named "d343_2"
step "Unfold1"
extrude "Extrude3" cut sketch "Sketch2" profile of L21 A19 A20 A21 L24 A22 L25 L27 L28 L29 no distance stored
step "Refold1"
face "EdgeFlange4" FlangeHeight 5.5 named "d345_2" FlangeAngle 0 named "d346_2"
face "EdgeFlange5" FlangeHeight 1.5 named "d347_2" FlangeAngle 45 named "d348_2"
face "EdgeFlange6" FlangeHeight 0.4 named "d349_2" FlangeAngle 65 named "d350_2"
face "EdgeFlange7" FlangeHeight 1.25 named "d351_2" FlangeAngle 85 named "d352_2"
rectangular_pattern "R-Pattern1" uSpaceDistance -2.5 named "d355_2" vSpaceDistance 0 named "d356_2"
rectangular_pattern "R-Pattern2" uSpaceDistance -7 named "d359_2" vSpaceDistance 0 named "d360_2"
rectangular_pattern "R-Pattern3" uSpaceDistance -2 named "d363_2" vSpaceDistance 0 named "d364_2"
work_plane "WorkPlane1" AlongDistance -13.14 (= "-10.28 mm - 2.71 mm - 0.15 mm") named "d288_1_1"
sketch "Sketch1" plane through (-4.64, 0, 15.975) normal (1, 0, 0) x axis (0, 1, 0)
  line L1 (3.8, -18.275) -> (3.598, -18.775)
  line L2 (3.8, -10.805) -> (3.8, -14.225)
  line L3 (3.2, -14.225) -> (3.2, -10.805)
  line L4 (3.8, -14.725) -> (3.8, -18.275)
  line L5 (3.2, -18.275) -> (3.2, -14.725)
  line L6 (3.2, -10.805) -> (3.8, -10.805)
  line L7 (3.598, -18.775) -> (3.402, -18.775)
  line L8 (3.402, -18.775) -> (3.2, -18.275)
  line L9 (3.7701, -0.925) -> (-3.7701, -0.925)
  line L10 (3.5, -18.775) -> (3.5, -10.805)
  line L11 (3.2, -14.475) -> (3.9, -14.475)
  line L12 (-5.95, -14.675) -> (-0.05, -14.675)
  line L13 (3.9, -14.225) -> (3.8, -14.225)
  line L14 (3.9, -14.725) -> (3.9, -14.225)
  line L15 (3.8, -14.725) -> (3.9, -14.725)
  line L16 (3.1, -14.725) -> (3.1, -14.225)
  line L17 (3.1, -14.225) -> (3.2, -14.225)
  line L18 (3.2, -14.725) -> (3.1, -14.725)
  point P16 (3.5, -10.805)
  point P17 (3.5, -18.775)
  point P8 (3.8, -18.275)
  point P12 (3.2, -18.275)
  point P6 (3.9, -14.475)
  point P10 (3.8, -14.725)
  point P26 (3.2, -14.725)
  point P11 (3.8, -14.225)
  point P25 (3.2, -14.225)
  point P21 (3.9, -14.225)
  point P23 (3.1, -14.225)
  point P22 (3.9, -14.725)
  point P24 (3.1, -14.725)
  point P4 (3.2, -14.225)
  point P9 (3.2, -14.725)
  point P15 (0, -15.975)
  point P1 (0, 0)
  vertical L3
  vertical L2
  collinear L2 L4
  collinear L3 L5
  horizontal L7
  horizontal L6
  midpoint L6 P16
  midpoint L7 P17
  horizontal L11
  symmetric P8 P12 L10
  perpendicular L2 L13
  perpendicular L13 L14
  horizontal L15
  midpoint P6 L14
  symmetric P10 L10 P26
  symmetric P11 L10 P25
  symmetric L10 P21 P23
  symmetric L10 P22 P24
  coincident P4 P25
  coincident P9 P26
  dimension "d289_1_1" distance L2 L3 = 0.6
  dimension "d295_1_1" distance L7 P15 = 2.8
  dimension "d300_1_1" distance P15 L11 = 1.5
  dimension "d301_1_1" distance P1 L10 = 3.5 (= "( 7 / 2 ) * 1 mm")
  dimension "d365_2" distance L6 L12 = 3.87 (= "5.12 mm - 1.25 mm")
  dimension "d366_2" angle L1 L4 = 22
  dimension "d367_2" distance P8 L7 = 0.5
  dimension "d368_2" distance P21 P22 = 0.5
  dimension "d369_2" distance L2 L14 = 0.1
face "Face1" sketch "Sketch1"
face "EdgeFlange2" FlangeHeight 1.5 named "d302_1_1" FlangeAngle 90 named "d303_1_1"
